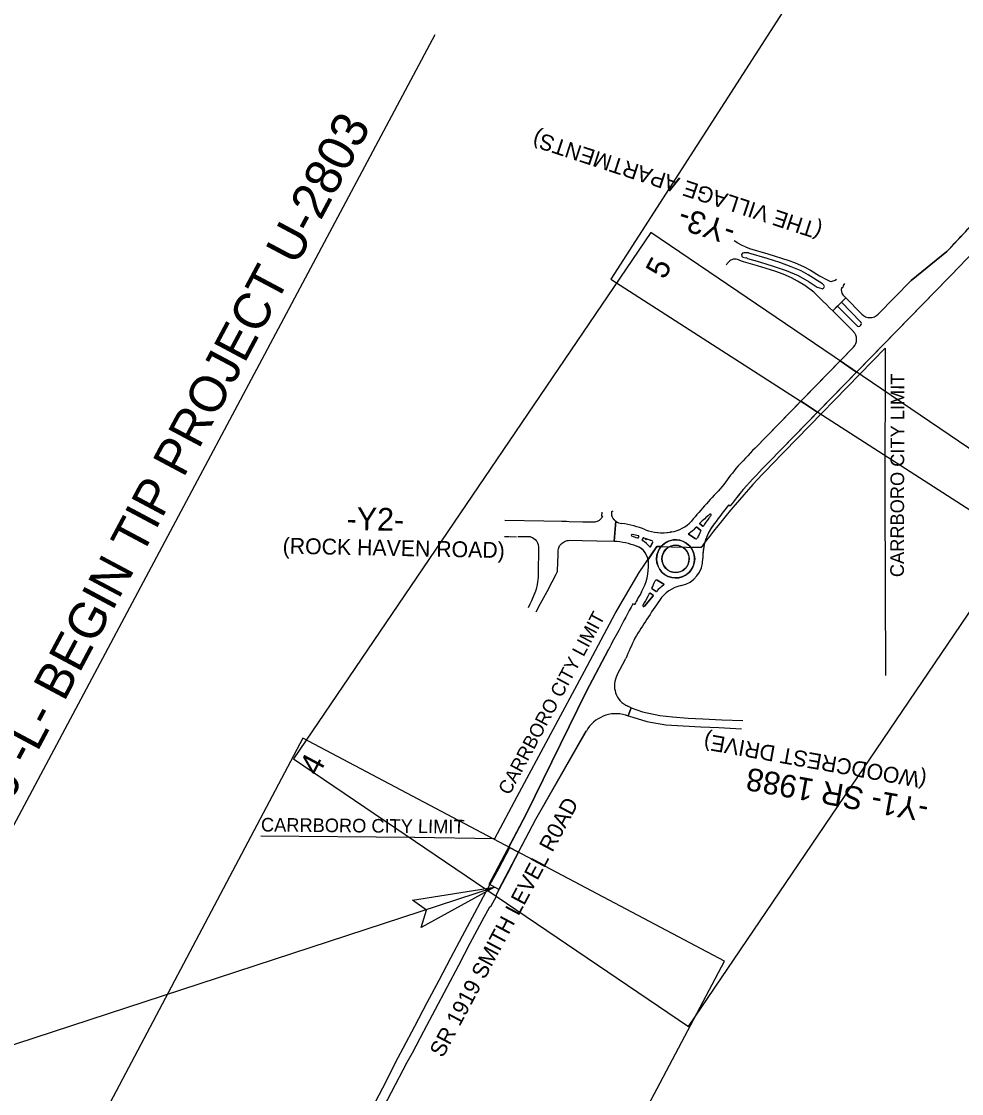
# Model space of a CAD drawing. Extents: x 1970823 to 1988115, y 770601 to 786368.
# Drawn here: x 1974936 to 1977005, y 778298 to 780658 of the extents above; entities that cross this region are included whole.
import ezdxf

# ---------------------------------------------------------------- set-up
doc = ezdxf.new("R2010")
doc.units = 0
for name, color, linetype in [('Old_Level_1', 7, 'Continuous'), ('Old_Level_11', 7, 'Continuous'), ('Old_Level_12', 7, 'Continuous'), ('Old_Level_3', 7, 'Continuous'), ('Old_Level_32', 7, 'Continuous'), ('Prop Conc 5in Monolithic Keyed In Island', 7, 'Continuous'), ('Prop EOT', 7, 'Continuous'), ('Prop Shade Heavy', 7, 'Continuous')]:
    doc.layers.add(name, color=color, linetype=linetype)

msp = doc.modelspace()

# ---------------------------------------------------------------- linework, layer by layer
at = {"layer": 'Old_Level_1'}
for q in [(1975846.6, 780629.7), (1975977.3, 778752)]:
    msp.add_line((1974607.5, 778304.3), q, dxfattribs=at)
for points in [[(1977116.1, 779523.4), (1977873.4, 780700.9), (1976990.2, 781268.9), (1976233, 780091.3)], [(1976403.9, 778445.7), (1977189.9, 779604.2), (1976321, 780193.7), (1975535, 779035.2)], [(1974902.4, 777845.2), (1975830.6, 777354.5), (1975830.6, 777354.5), (1976483.5, 778589.6), (1976483.5, 778589.6), (1975555.2, 779080.3), (1975555.2, 779080.3)]]:
    msp.add_lwpolyline(points, close=True, dxfattribs=at)
at = {"layer": 'Old_Level_11'}
msp.add_lwpolyline([(1975796.9, 778723.9), (1975977.3, 778752), (1975816, 778663.9), (1975827.6, 778701.6)], close=True, dxfattribs=at)
at = {"layer": 'Old_Level_12'}
for p, q in [((1976586.9, 779682.3), (1976837.1, 779939)), ((1976295.6, 779444.8), (1976334.6, 779502.4)), ((1976334.6, 779502.4), (1976432.1, 779500.4)), ((1976243.1, 779355.2), (1976295.6, 779444.8)), ((1976175, 779228.2), (1976243.1, 779355.2)), ((1976027.4, 778952), (1976175, 779228.2))]:
    msp.add_line(p, q, dxfattribs=at)
for points in [[(1976837.1, 779939), (1976836.2, 779613), (1976838, 779218.7)], [(1975463.2, 778865.5), (1975800.9, 778862.2), (1975978.1, 778859.8), (1976027.4, 778952)]]:
    msp.add_lwpolyline(points, dxfattribs=at)
msp.add_arc((1977861.3, 778440.4), 1779.3, 135.7394, 143.4363, dxfattribs=at)
at = {"layer": 'Old_Level_3'}
for p, q in [((1976741.8, 780072.8), (1976743.5, 780072.4)), ((1976714.7, 780028.1), (1976707.6, 780035.1)), ((1976011.7, 779524.2), (1976025.6, 779524))]:
    msp.add_line(p, q, dxfattribs=at)
for points in [[(1976529.4, 780161.9), (1976522.5, 780165.3), (1976512.6, 780170.3), (1976504.5, 780175.3)], [(1976529.4, 780161.9), (1976538.6, 780158.7)], [(1976536.8, 780148.5), (1976536.3, 780148.6), (1976526, 780149.2), (1976522.8, 780148.1), (1976520.6, 780145.3), (1976521.4, 780141.5), (1976523.7, 780139.7), (1976530.7, 780137.6)], [(1976534, 780136.8), (1976530.8, 780137.6)], [(1976534, 780136.8), (1976560.6, 780129.2), (1976590.8, 780119.7), (1976619.3, 780110.4), (1976645.7, 780098.8), (1976669.4, 780085.3), (1976687.6, 780073.4), (1976697.7, 780070.1), (1976700.1, 780069.9), (1976702, 780072), (1976703.2, 780074.7), (1976702, 780078), (1976698.9, 780080.9), (1976667.7, 780100.5), (1976651.9, 780109), (1976630.4, 780118.4), (1976604.9, 780127.7), (1976577.2, 780136.7), (1976536.9, 780148.4)], [(1976538.7, 780158.7), (1976578.5, 780146.5), (1976625, 780131.8), (1976637.2, 780127.8), (1976659, 780118.3), (1976672.7, 780110.9), (1976692.5, 780098.5), (1976709.1, 780089.3), (1976715.2, 780086.5), (1976718.4, 780086.2), (1976727.1, 780088.7), (1976729.7, 780091.2)], [(1976707.6, 780035.1), (1976700.6, 780042.1), (1976679.8, 780062.2), (1976660.3, 780077.1), (1976644.1, 780086.9), (1976630.8, 780093.7), (1976612.5, 780102), (1976594.1, 780108.5), (1976555.9, 780120), (1976525.3, 780129.2)], [(1976750.3, 780050.1), (1976746.4, 780054.1), (1976742.3, 780060.1), (1976741, 780067.2), (1976741.8, 780072.8)], [(1976747.3, 780081.4), (1976744.7, 780076.8), (1976743.5, 780072.4)], [(1976721.5, 780021.5), (1976714.7, 780028.1)], [(1976213.2, 779577.8), (1976213, 779570.1), (1976214.7, 779569.2)], [(1976235.5, 779579.4), (1976238.4, 779581)], [(1976192, 779555.7), (1976171.6, 779556.2), (1976141.4, 779557), (1976135.7, 779557.1), (1976131.3, 779557.2), (1976125.3, 779557.3), (1976085.7, 779558.1), (1975999.9, 779559.9)], [(1975999.1, 779524.5), (1976010.6, 779524.3)], [(1976056.8, 779523.4), (1976049.9, 779523.4), (1976028.4, 779523.9)], [(1976056.6, 779523.4), (1976060.9, 779521.9), (1976064.1, 779520.2), (1976066.9, 779517.9), (1976070.7, 779513.6), (1976072, 779510.8), (1976073.5, 779506.5), (1976074, 779500.8), (1976073.8, 779482), (1976073.3, 779460), (1976073, 779439.3), (1976073, 779435), (1976070.9, 779418.8), (1976069.1, 779408.5), (1976067.8, 779404.2), (1976058.7, 779382.4), (1976055.3, 779375.3), (1976051.3, 779367.5)], [(1976142.8, 779516.1), (1976169.9, 779515.5), (1976202.1, 779514.8), (1976238.9, 779514)], [(1976068.9, 779358.7), (1976078.8, 779376.7), (1976093.2, 779403.5), (1976104.3, 779424.5), (1976113.1, 779441.4), (1976114.4, 779444.2), (1976115.3, 779446.2), (1976116, 779448.2), (1976116.2, 779449.8), (1976117.3, 779484), (1976117.4, 779493.6), (1976117.5, 779494.4)], [(1976068.8, 779358.2), (1976068.9, 779358.7)], [(1976278.1, 779147.2), (1976302.7, 779138.6), (1976340.9, 779130.1), (1976368.7, 779127), (1976403.8, 779124.3), (1976435.7, 779122.6), (1976477.7, 779120.7), (1976524, 779119.1)], [(1976271.6, 779129.7), (1976281.6, 779126.6), (1976312.5, 779117), (1976354, 779110), (1976392.8, 779107.3), (1976431.2, 779105.6), (1976470.7, 779104), (1976521, 779101.2)], [(1975986.4, 778793.7), (1976010.8, 778839.4)], [(1976006.3, 778783), (1976030.4, 778829.1)], [(1975776.4, 778398), (1975801.7, 778446.2), (1975829.1, 778498.1), (1975855.3, 778547.7), (1975881.3, 778597), (1975906.9, 778645.3), (1975933.6, 778695.5), (1975958.6, 778742.5), (1975986.4, 778793.7)], [(1975796.4, 778387.4), (1975821.7, 778435.2), (1975847.5, 778483.8), (1975873, 778532.1), (1975898.6, 778580.8), (1975924, 778629.1), (1975950.1, 778678.4), (1975967, 778708.9), (1975969.6, 778711.2), (1975980.8, 778730.9), (1975982.6, 778737.8), (1976006.3, 778783)], [(1975572.1, 777985.9), (1975581.2, 778008.3), (1975595.3, 778040.6), (1975616.5, 778084.7), (1975640.5, 778133), (1975672.6, 778197.2), (1975700.2, 778250.6), (1975731.3, 778310.8), (1975765.5, 778377.1), (1975776.4, 778398)], [(1975592.2, 777977.8), (1975601, 778000), (1975614.9, 778031.5), (1975635.9, 778075), (1975659.8, 778123.4), (1975692, 778187.7), (1975719.2, 778240.6), (1975750.5, 778300.9), (1975784.7, 778367), (1975796.4, 778387.4)]]:
    msp.add_lwpolyline(points, dxfattribs=at)
for points in [[(1976525.1, 780129.4), (1976517.2, 780132.2), (1976506.1, 780135.1), (1976499.7, 780133.7), (1976491.9, 780128.3), (1976487.1, 780122.3)], [(1976244, 779558), (1976243.1, 779558.8), (1976242.1, 779559.7), (1976241.3, 779560.6), (1976240.8, 779561.1), (1976240.4, 779561.5), (1976239.7, 779562.4), (1976239, 779563.3), (1976238.3, 779564.3), (1976237.7, 779565.3), (1976237.6, 779565.6), (1976236.4, 779567.8), (1976235.9, 779569.2), (1976235.7, 779569.9), (1976235.7, 779570.6), (1976235.5, 779579.4)], [(1976214.7, 779569.2), (1976211.8, 779564.4), (1976208.7, 779560.9), (1976203.2, 779557.5), (1976192, 779555.7)], [(1976117.5, 779494.4), (1976120.5, 779503.9), (1976124.8, 779508.7), (1976132.3, 779513.7), (1976142.8, 779516.1)]]:
    msp.add_spline(points, degree=3, dxfattribs=at)
at = {"layer": 'Prop Conc 5in Monolithic Keyed In Island'}
for p, q in [((1976293.7, 779521.2), (1976294.9, 779524.5)), ((1976404.4, 779529.4), (1976419.2, 779519.7)), ((1976304.5, 779521.3), (1976302.5, 779516.6)), ((1976320.4, 779501.8), (1976325.2, 779511.5)), ((1976334.9, 779428.2), (1976349.8, 779419.5)), ((1976307.2, 779370.9), (1976326.7, 779394)), ((1976319.9, 779399.7), (1976326.4, 779395.5))]:
    msp.add_line(p, q, dxfattribs=at)
for points in [[(1976429, 779552.2), (1976435.6, 779547.1)], [(1976293.7, 779521.2), (1976294.9, 779524.5)], [(1976404.4, 779529.4), (1976419.2, 779519.7)], [(1976431.1, 779537.9), (1976422.3, 779544.7)], [(1976304.5, 779521.3), (1976302.5, 779516.6)], [(1976311.1, 779519.6), (1976309.8, 779516.7), (1976311.1, 779519.6)], [(1976320.4, 779501.8), (1976325.2, 779511.5)], [(1976323.9, 779409), (1976332.8, 779403.3)], [(1976349.8, 779419.5), (1976334.9, 779428.2)], [(1976307.2, 779370.9), (1976326.7, 779394)], [(1976326.4, 779395.5), (1976319.9, 779399.7)]]:
    msp.add_lwpolyline(points, dxfattribs=at)
for centre, radius, start, end in [((1977729.6, 778130.3), 1928.2, 131.5446, 132.4191), ((1977729.6, 778130.3), 1928.2, 131.5446, 132.4191), ((1977926.9, 778377.9), 1895.5, 141.0068, 141.2395), ((1977926.9, 778377.9), 1895.5, 141.0068, 141.2395), ((1976452.2, 779571.9), 2, 321.0068, 131.5446), ((1976452.2, 779571.9), 2, 321.0068, 131.5446), ((1976429.6, 779553), 1, 132.4191, 231.9065), ((1976429.6, 779553), 1, 132.4191, 231.9065), ((1976436.2, 779547.8), 1, 231.9065, 330.018), ((1976436.2, 779547.8), 1, 231.9065, 330.018), ((1976555.7, 779478.9), 137, 141.2395, 150.018), ((1976555.7, 779478.9), 137, 141.2395, 150.018), ((1976280.2, 779526.8), 2, 79.4395, 253.1009), ((1976280.2, 779526.8), 2, 79.4395, 253.1009), ((1976221.4, 779333.1), 200.4, 69.2746, 73.1009), ((1976221.4, 779333.1), 200.4, 69.2746, 73.1009), ((1976243.4, 779329.6), 202.6, 75.4924, 79.4395), ((1976243.4, 779329.6), 202.6, 75.4924, 79.4395), ((1976293.9, 779524.8), 1, 340.6492, 75.4924), ((1976293.9, 779524.8), 1, 340.6492, 75.4924), ((1976405, 779530.2), 1, 122.6674, 236.722), ((1976405, 779530.2), 1, 122.6674, 236.722), ((1976354.8, 779608.5), 92, 302.6674, 316.0364), ((1976354.8, 779608.5), 92, 302.6674, 316.0364), ((1976421.7, 779543.9), 1, 52.2081, 136.0364), ((1976421.7, 779543.9), 1, 52.2081, 136.0364), ((1976548.8, 779468.2), 135.8, 149.792, 157.1435), ((1976548.8, 779468.2), 135.8, 149.792, 157.1435), ((1976430.5, 779537.1), 1, 329.792, 52.2081), ((1976430.5, 779537.1), 1, 329.792, 52.2081), ((1976292.8, 779521.5), 1, 241.0006, 340.6492), ((1976292.8, 779521.5), 1, 241.0006, 340.6492), ((1976303.5, 779516.2), 1, 157.7992, 238.9047), ((1976303.5, 779516.2), 1, 157.7992, 238.9047), ((1976271.5, 779463.1), 61, 39.1963, 58.9047), ((1976271.5, 779463.1), 61, 39.1963, 58.9047), ((1976305.4, 779520.9), 1, 66.3367, 157.7992), ((1976305.4, 779520.9), 1, 66.3367, 157.7992), ((1976352.7, 779628.9), 116.9, 246.3367, 255.4103), ((1976352.7, 779628.9), 116.9, 246.3367, 249.1392), ((1976352.7, 779628.9), 116.9, 249.1392, 255.4103), ((1976319.5, 779502.3), 1, 219.1963, 333.6015), ((1976319.5, 779502.3), 1, 219.1963, 333.6015), ((1976322.5, 779512.8), 3, 333.6015, 75.4103), ((1976322.5, 779512.8), 3, 333.6015, 75.4103), ((1976375.8, 779475.1), 42, 55.3305, 235.3305), ((1976375.8, 779475.1), 30, 55.1797, 235.1797), ((1976375.8, 779475.1), 42, 235.3305, 55.3305), ((1976375.8, 779475.1), 30, 235.1797, 55.1797), ((1976420.8, 779522.2), 3, 236.722, 337.1435), ((1976420.8, 779522.2), 3, 236.722, 337.1435), ((1976333.4, 779425.6), 3, 59.8207, 160.4471), ((1976333.4, 779425.6), 3, 59.8207, 160.4471), ((1976324.4, 779409.9), 1, 152.9755, 237.2513), ((1976324.4, 779409.9), 1, 152.9755, 237.2513), ((1976202, 779472.3), 136.4, 332.9755, 340.4471), ((1976202, 779472.3), 136.4, 332.9755, 340.4471), ((1976403.4, 779343), 92, 125.5201, 138.8781), ((1976403.4, 779343), 92, 125.5201, 138.8781), ((1976349.3, 779418.7), 1, 305.5201, 59.8207), ((1976349.3, 779418.7), 1, 305.5201, 59.8207), ((1977680.5, 778615.6), 1571.2, 150.3557, 151.1771), ((1977680.5, 778615.6), 1571.2, 150.3557, 151.1771), ((1976196.2, 779461.3), 137.1, 330.0114, 333.1049), ((1976196.2, 779461.3), 137.1, 330.0114, 333.1049), ((1976319.4, 779398.8), 1, 57.5529, 153.1049), ((1976319.4, 779398.8), 1, 57.5529, 153.1049), ((1976325.9, 779394.7), 1, 319.9706, 57.5529), ((1976325.9, 779394.7), 1, 319.9706, 57.5529), ((1976333.3, 779404.1), 1, 237.2513, 318.8781), ((1976333.3, 779404.1), 1, 237.2513, 318.8781), ((1976305.7, 779372.1), 2, 151.1771, 319.9706), ((1976305.7, 779372.1), 2, 151.1771, 319.9706)]:
    msp.add_arc(centre, radius, start, end, dxfattribs=at)
at = {"layer": 'Prop EOT'}
for p, q in [((1976894, 780088.4), (1976972.4, 780151.6)), ((1976972.4, 780151.6), (1976974.3, 780153.6)), ((1976581.6, 779689), (1977005.1, 780123.6)), ((1976821.5, 780013.9), (1976894, 780088.4)), ((1976721.5, 780021.5), (1976750.3, 780050.1)), ((1976750.3, 780050.1), (1976785.8, 780013.8)), ((1976721.5, 780021.5), (1976767, 779976)), ((1976732.2, 780031.6), (1976774.5, 779988.8)), ((1976740.9, 780040.3), (1976783.1, 779997.3)), ((1976550.8, 779719), (1976767.1, 779941)), ((1976492.7, 779594.4), (1976495.8, 779591.9)), ((1976240.8, 779513.9), (1976244, 779558)), ((1976281.8, 779376.5), (1976285.3, 779374.5)), ((1976178.7, 779182.3), (1976228.2, 779275.9)), ((1976247, 779219.5), (1976266, 779255.5)), ((1976047.1, 778913), (1976178.7, 779182.3)), ((1976278.1, 779147.2), (1976270.5, 779150.7)), ((1976278.1, 779147.2), (1976271.6, 779129.6)), ((1976271.6, 779129.6), (1976266, 779131.2)), ((1976068.3, 778901.8), (1976179.3, 779096.5)), ((1975965.6, 778758.8), (1976047.1, 778913)), ((1975986.6, 778747.3), (1976068.3, 778901.8)), ((1976008.8, 778840.5), (1976030, 778829.3))]:
    msp.add_line(p, q, dxfattribs=at)
for radius in [42, 30]:
    msp.add_circle((1976375.8, 779475.1), radius, dxfattribs=at)
for centre, radius, start, end in [((1975987.1, 781115.7), 1378.5, 315.7395, 320.5086), ((1975987.1, 781115.7), 1421.5, 315.7395, 321.4059), ((1976778.8, 779993.1), 6, 314.6608, 44.4765), ((1976803.6, 780031.4), 25, 224.7243, 315.7395), ((1976749.2, 779958.4), 25, 315.7395, 44.7243), ((1976778.7, 779993), 6, 224.6608, 314.6608), ((1977926.9, 778377.9), 1921.5, 135.7395, 137.5783), ((1977926.9, 778377.9), 1878.5, 135.7395, 138.2839), ((1978028, 778491.5), 1925.5, 142.1057, 143.6134), ((1977876.3, 778316.7), 1921, 136.7176, 139.7332), ((1977976, 778436), 1878, 140.5977, 142.0125), ((1977976.4, 778436.4), 1882, 142.0289, 143.6297), ((1976258.8, 779577.5), 24.5, 232.7665, 266.0897), ((1976227.7, 779333.2), 221.8, 68.3898, 82.3776), ((1976354.8, 779608.5), 75, 278.9494, 318.0674), ((1976555.7, 779478.9), 120, 142.1787, 181.1936), ((1976346.2, 779632.4), 100, 248.3898, 280.6337), ((1976375.8, 779475.1), 60, 98.9494, 101.7975), ((1976227.7, 779333.2), 181, 69.8927, 85.8568), ((1976276.2, 779465.7), 40, 0.1217, 69.8927), ((1976375.8, 779475.1), 60, 281.7976, 1.1936), ((1976196.2, 779461.3), 120.1, 330.7248, 2.1178), ((1976403.4, 779343), 75, 101.7976, 147.0005), ((1977970.7, 778451.4), 1921.7, 150.3325, 151.2896), ((1977887.9, 778312.7), 1882, 145.31, 148.3291), ((1977970.7, 778451.4), 1925.7, 151.2896, 153.2826), ((1977926.9, 778377.9), 1921.5, 150.7331, 152.1381), ((1977999.7, 778511.4), 1886.6, 155.2633, 156.7713), ((1976291.2, 779196.2), 50, 152.1381, 245.532), ((1976244.7, 779059.3), 75, 73.5208, 150.5633)]:
    msp.add_arc(centre, radius, start, end, dxfattribs=at)
at = {"layer": 'Prop Shade Heavy'}
for p, q in [((1976972.4, 780151.6), (1976894, 780088.4)), ((1976974.3, 780153.6), (1976972.4, 780151.6)), ((1976774, 779886.4), (1977005.1, 780123.6)), ((1976894, 780088.4), (1976821.5, 780013.9)), ((1976750.3, 780050.1), (1976740.7, 780040.5)), ((1976785.8, 780013.8), (1976750.3, 780050.1)), ((1976731.9, 780031.9), (1976721.5, 780021.5)), ((1976721.5, 780021.5), (1976767, 779976)), ((1976774.5, 779988.8), (1976732.2, 780031.6)), ((1976740.9, 780040.3), (1976783.1, 779997.3)), ((1976767.1, 779941), (1976737.8, 779910.9)), ((1976737.8, 779910.9), (1976651.4, 779822.2)), ((1976774, 779886.4), (1976737.8, 779910.9)), ((1976737.8, 779910.9), (1976774, 779886.4)), ((1976688.3, 779798.5), (1976774, 779886.4)), ((1976651.4, 779822.2), (1976550.8, 779719)), ((1976651.4, 779822.2), (1976688.3, 779798.5)), ((1976688.3, 779798.5), (1976651.4, 779822.2)), ((1976581.6, 779689), (1976688.3, 779798.5)), ((1976492.7, 779594.4), (1976495.8, 779591.9)), ((1976244, 779558), (1976240.8, 779513.8)), ((1976435.6, 779547.1), (1976429, 779552.2)), ((1976294.9, 779524.5), (1976293.7, 779521.2)), ((1976419.2, 779519.7), (1976404.4, 779529.4)), ((1976422.3, 779544.7), (1976431.1, 779537.9)), ((1976302.5, 779516.6), (1976304.5, 779521.3)), ((1976334.6, 779502.4), (1976315.3, 779474)), ((1976315.3, 779474), (1976334.6, 779502.4)), ((1976325.2, 779511.5), (1976320.4, 779501.8)), ((1976343.7, 779502.2), (1976334.6, 779502.4)), ((1976334.6, 779502.4), (1976343.7, 779502.2)), ((1976432.1, 779500.4), (1976408.9, 779500.9)), ((1976408.9, 779500.9), (1976432.1, 779500.4)), ((1976332.8, 779403.3), (1976323.9, 779409)), ((1976334.9, 779428.2), (1976349.8, 779419.5)), ((1976326.7, 779394), (1976307.2, 779370.9)), ((1976319.9, 779399.7), (1976326.4, 779395.5)), ((1976285.3, 779374.5), (1976281.8, 779376.5)), ((1976228.2, 779275.9), (1976178.7, 779182.3)), ((1976247, 779219.5), (1976266, 779255.5)), ((1976178.7, 779182.3), (1976047.1, 778913)), ((1976278.1, 779147.2), (1976270.5, 779150.7)), ((1976271.6, 779129.6), (1976278.1, 779147.2)), ((1976266, 779131.2), (1976271.6, 779129.6)), ((1976068.3, 778901.8), (1976179.4, 779096.2)), ((1976047.1, 778913), (1976008.8, 778840.5)), ((1976030, 778829.3), (1976068.3, 778901.8)), ((1976008.8, 778840.5), (1976010.8, 778839.5)), ((1976010.8, 778839.5), (1976030, 778829.3))]:
    msp.add_line(p, q, dxfattribs=at)
for points in [[(1976732.2, 780031.6), (1976731.9, 780031.9)], [(1976740.7, 780040.5), (1976740.9, 780040.3)], [(1976783, 779988.8), (1976782.9, 779988.8)], [(1976524.7, 779628), (1976524.8, 779628.1)], [(1976364.7, 779534.1), (1976363.5, 779533.9), (1976363.5, 779533.9)], [(1976250.7, 779317.3), (1976250.6, 779317.2)]]:
    msp.add_lwpolyline(points, dxfattribs=at)
msp.add_lwpolyline([(1975965.6, 778758.8), (1976008.8, 778840.5), (1976030, 778829.3), (1975986.6, 778747.3)], close=True, dxfattribs=at)
for centre, radius, start, end in [((1975987.1, 781115.7), 1378.5, 315.7395, 340.6265), ((1975987.1, 781115.7), 1421.5, 315.7395, 321.4059), ((1976778.8, 779993.1), 6, 314.6608, 44.4765), ((1976803.6, 780031.4), 25, 224.7243, 315.7395), ((1976749.2, 779958.4), 25, 315.7395, 44.7243), ((1976778.7, 779993), 6, 224.6608, 314.6608), ((1977926.9, 778377.9), 1921.5, 135.7395, 137.5783), ((1977926.9, 778377.9), 1878.5, 135.7395, 138.2814), ((1978028, 778491.5), 1925.5, 142.1057, 143.6134), ((1977876.3, 778316.7), 1921, 136.7176, 139.7332), ((1977976, 778436), 1878, 140.6002, 142.0125), ((1977926.9, 778377.9), 1878.5, 138.2814, 138.2839), ((1977976, 778436), 1878, 140.5977, 140.6002), ((1977976.4, 778436.4), 1882, 142.0289, 143.6297), ((1977729.6, 778130.3), 1928.2, 131.5446, 132.4191), ((1977926.9, 778377.9), 1895.5, 141.0068, 141.2395), ((1976452.2, 779571.9), 2, 358.4837, 131.5446), ((1976452.2, 779571.9), 2, 321.0068, 358.4837), ((1976258.8, 779577.5), 24.5, 232.7665, 266.0897), ((1976227.7, 779333.2), 221.8, 68.3898, 82.3776), ((1976354.8, 779608.5), 75, 278.9494, 318.0674), ((1976429.6, 779553), 1, 132.4191, 231.9065), ((1976436.2, 779547.8), 1, 231.9065, 330.018), ((1976555.7, 779478.9), 137, 141.2395, 150.018), ((1976555.7, 779478.9), 120, 142.1787, 164.3834), ((1976280.2, 779526.8), 2, 79.4395, 253.1009), ((1976221.4, 779333.1), 200.4, 69.2746, 73.1009), ((1976243.4, 779329.6), 202.6, 75.4924, 79.4395), ((1976293.9, 779524.8), 1, 340.6492, 75.4924), ((1976346.2, 779632.4), 100, 248.3898, 279.9356), ((1976375.8, 779475.1), 60, 98.9494, 100.6337), ((1976405, 779530.2), 1, 122.6674, 236.722), ((1976354.8, 779608.5), 92, 302.6674, 316.0364), ((1976421.7, 779543.9), 1, 52.2081, 136.0364), ((1976548.8, 779468.2), 135.8, 149.792, 157.1435), ((1976430.5, 779537.1), 1, 329.792, 52.2081), ((1976227.7, 779333.2), 181, 69.8927, 85.8568), ((1976276.2, 779465.7), 40, 11.9881, 69.8927), ((1976292.8, 779521.5), 1, 241.0006, 340.6492), ((1976303.5, 779516.2), 1, 157.7992, 238.9047), ((1976271.5, 779463.1), 61, 39.1963, 58.9047), ((1976305.4, 779520.9), 1, 66.3367, 157.7992), ((1976352.7, 779628.9), 116.9, 246.3367, 255.4103), ((1976319.5, 779502.3), 1, 219.1963, 333.6015), ((1976322.5, 779512.8), 3, 333.6015, 75.4103), ((1976375.8, 779475.1), 42, 139.8365, 37.8387), ((1976375.8, 779475.1), 42, 55.3305, 139.8365), ((1976375.8, 779475.1), 42, 37.8387, 55.3305), ((1976420.8, 779522.2), 3, 236.722, 337.1435), ((1977861.3, 778440.4), 1779.3, 143.0037, 143.4363), ((1977861.3, 778440.4), 1779.3, 143.0037, 143.4363), ((1976555.7, 779478.9), 120, 164.3834, 181.1936), ((1976375.8, 779475.1), 60, 281.7976, 1.1936), ((1976196.2, 779461.3), 120.1, 330.7248, 2.1178), ((1976276.2, 779465.7), 40, 0.1217, 11.9881), ((1976333.4, 779425.6), 3, 59.8207, 160.4471), ((1976324.4, 779409.9), 1, 152.9755, 237.2513), ((1976202, 779472.3), 136.4, 332.9755, 340.4471), ((1976403.4, 779343), 92, 125.5201, 138.8781), ((1976403.4, 779343), 75, 101.7976, 147.0005), ((1976349.3, 779418.7), 1, 305.5201, 59.8207), ((1977970.7, 778451.4), 1921.7, 150.3325, 151.2896), ((1977887.9, 778312.7), 1882, 145.31, 148.3291), ((1977680.5, 778615.6), 1571.2, 150.3557, 151.1771), ((1976196.2, 779461.3), 137.1, 330.0114, 333.1049), ((1976319.4, 779398.8), 1, 57.5529, 153.1049), ((1976325.9, 779394.7), 1, 319.9706, 57.5529), ((1976333.3, 779404.1), 1, 237.2513, 318.8781), ((1977970.7, 778451.4), 1925.7, 151.2896, 153.2799), ((1976305.7, 779372.1), 2, 151.1771, 319.9706), ((1977926.9, 778377.9), 1921.5, 150.7357, 152.1381), ((1977970.7, 778451.4), 1925.7, 153.2799, 153.2826), ((1977926.9, 778377.9), 1921.5, 150.7331, 150.7357), ((1977999.7, 778511.4), 1886.6, 155.2633, 156.7713), ((1976291.2, 779196.2), 50, 152.1381, 245.532), ((1976244.7, 779059.3), 75, 73.5208, 150.5633)]:
    msp.add_arc(centre, radius, start, end, dxfattribs=at)

# ---------------------------------------------------------------- texts
at = {"layer": 'Old_Level_1'}
for s, height, rotation, p in [('STA.  13+00.00 -L- BEGIN TIP PROJECT U-2803', 80, 61.9471, (1974589.4, 778332.2)), ('(THE VILLAGE APARTMENTS)', 35, 161.8664, (1976701, 780210.6)), ('-Y3-', 50, 161.8664, (1976511.1, 780212.4)), ('5', 50, 61.9471, (1976351.5, 780088.3)), ('-Y2- ', 50, 358.8319, (1975651.5, 779539)), ('(ROCK HAVEN ROAD)', 35, 358.8319, (1975510.7, 779486.7)), ('(WOODCREST DRIVE)', 35, 169.8668, (1976930.1, 779003.4)), ('4', 50, 61.9471, (1975589.2, 778994.8)), ('-Y1- SR 1988', 50, 169.8668, (1976935.3, 778944.6)), ('SR 1919 SMITH LEVEL R0AD', 35, 61.9471, (1975863.6, 778375.2))]:
    msp.add_text(s, height=height, rotation=rotation, dxfattribs=at).set_placement(p)
at = {"layer": 'Old_Level_32'}
for rotation, p in [(89.85, (1976878.2, 779434.9)), (61.884, (1976010.2, 778953.3)), (359.4292, (1975463.2, 778875))]:
    msp.add_text('CARRBORO CITY LIMIT', height=30, rotation=rotation, dxfattribs=at).set_placement(p)

doc.saveas('drawing.dxf')
